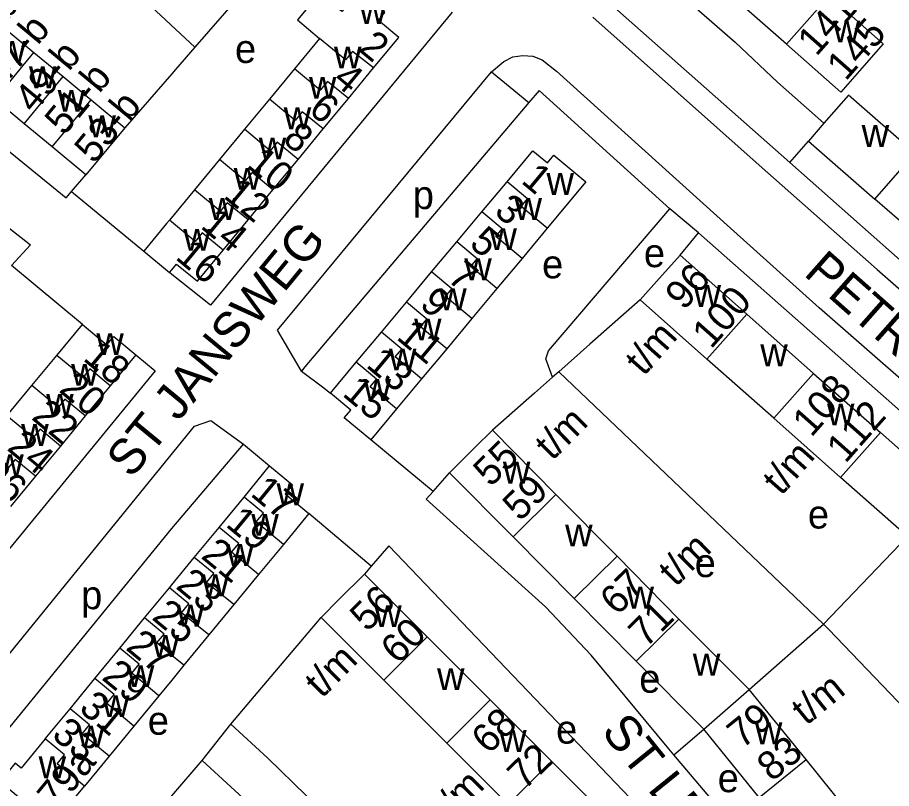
# Model space of a CAD drawing. Extents: x 161141 to 163125, y 381621 to 383200.
# Drawn here: x 162578.3 to 162701.2, y 382067.8 to 382176.1 of the extents above; entities that cross this region are included whole.
import ezdxf

# ---------------------------------------------------------------- set-up
doc = ezdxf.new("R2010")
doc.units = 0
for name, color, linetype in [('BLT_Basislijn', 7, 'Continuous'), ('BLT_Bebouwing', 7, 'Continuous'), ('BLT_Centroide', 7, 'Continuous'), ('BLT_Huisnummer', 7, 'Continuous'), ('BLT_Huisnummer_ tussenligend', 7, 'Continuous'), ('BLT_Huisnummer_reeks', 7, 'Continuous'), ('BLT_Onderverdeling_panden', 7, 'Continuous'), ('BLT_Straatnaam', 7, 'Continuous')]:
    doc.layers.add(name, color=color, linetype=linetype)

msp = doc.modelspace()

# ---------------------------------------------------------------- linework, layer by layer
at = {"layer": 'BLT_Basislijn'}
for p, q in [((162603.24, 382171.92), (162552.11, 382219.68)), ((162627.91, 382207.82), (162686.86, 382155.75)), ((162612.62, 382182.69), (162603.24, 382171.92)), ((162659.18, 382176.13), (162682.55, 382155.38)), ((162603.24, 382171.92), (162600.54, 382168.81)), ((162644.95, 382168.48), (162646.65, 382169.93)), ((162646.65, 382169.93), (162647.92, 382170.57)), ((162647.92, 382170.57), (162649.32, 382170.78)), ((162649.32, 382170.78), (162650.74, 382170.65)), ((162650.74, 382170.65), (162652.07, 382170.16)), ((162652.07, 382170.16), (162654.06, 382168.58)), ((162614.87, 382132.2), (162644.95, 382168.48)), ((162644.95, 382168.48), (162650.18, 382164.18)), ((162678.53, 382146.52), (162654.06, 382168.58)), ((162669.99, 382149.24), (162651.61, 382165.86)), ((162686.86, 382155.75), (162689.47, 382158.75)), ((162682.55, 382155.38), (162699.16, 382140.69)), ((162686.86, 382155.75), (162723.9, 382122.88)), ((162585.92, 382151.66), (162587.92, 382153.99)), ((162585.92, 382151.66), (162596.05, 382143.29)), ((162674.05, 382145.84), (162669.99, 382149.24)), ((162690.97, 382135.31), (162678.53, 382146.52)), ((162671.43, 382142.74), (162674.05, 382145.84)), ((162711.69, 382112.59), (162674.05, 382145.84)), ((162587.43, 382132.98), (162577.47, 382141.26)), ((162699.16, 382140.69), (162721.48, 382120.96)), ((162665.84, 382136.43), (162658.77, 382130.2)), ((162705.55, 382122.59), (162690.97, 382135.31)), ((162618.22, 382126.43), (162614.87, 382132.2)), ((162658.77, 382130.2), (162654.39, 382126.34)), ((162653.5, 382125.56), (162650.99, 382123.34)), ((162654.39, 382126.34), (162653.5, 382125.56)), ((162654.39, 382126.34), (162691.58, 382090.88)), ((162650.99, 382123.34), (162645.07, 382118.13)), ((162603.17, 382118.72), (162605.5, 382119.51)), ((162605.5, 382119.51), (162610.06, 382116.17)), ((162564.06, 382070.63), (162603.17, 382118.72)), ((162636.73, 382109.54), (162627.96, 382116.77)), ((162636.73, 382109.54), (162639.05, 382112.16)), ((162628.03, 382099.03), (162619.27, 382106.45)), ((162691.58, 382090.88), (162703.38, 382103.2)), ((162628.03, 382099.03), (162627.07, 382097.93)), ((162611.6, 382080.77), (162620.99, 382091.84)), ((162681.17, 382081.7), (162691.58, 382090.88)), ((162608.29, 382076.86), (162611.6, 382080.77)), ((162670.57, 382072.53), (162674.76, 382076.14))]:
    msp.add_line(p, q, dxfattribs=at)
for points in [[(162632.9, 382213.4), (162647.43, 382200.65), (162654.07, 382194.55), (162679.17, 382172.65), (162685.13, 382167), (162691.65, 382161.24)], [(162528.71, 382196.77), (162585.17, 382150.79), (162585.92, 382151.66)], [(162523.31, 382189.92), (162527.71, 382186.06), (162546.39, 382170.58), (162580.13, 382144.17), (162577.47, 382141.26)], [(162639.4, 382176.86), (162605.45, 382135.68), (162600, 382140.02), (162599.68, 382140.28)], [(162600.54, 382168.81), (162600, 382168.19), (162593.39, 382160.61)], [(162651.61, 382165.86), (162650.18, 382164.18)], [(162650.18, 382164.18), (162618.7, 382127.04), (162618.22, 382126.43)], [(162653.5, 382125.56), (162652.55, 382128.18), (162652.96, 382129.27), (162669.99, 382149.24)], [(162594.95, 382128.72), (162597.67, 382126.47), (162566.95, 382089.09), (162559.73, 382080.45)], [(162618.22, 382126.43), (162621.18, 382124.21), (162622.29, 382123.35)], [(162569.16, 382066.59), (162600, 382104.33), (162610.06, 382116.17)], [(162610.06, 382116.17), (162613.75, 382113.11)], [(162670.57, 382072.53), (162669.87, 382073.36), (162658.96, 382086.55), (162652.5, 382093.32), (162635.73, 382108.43), (162636.73, 382109.54)], [(162665.45, 382065.37), (162630.49, 382101.88), (162628.03, 382099.03)], [(162691.58, 382090.88), (162692.35, 382090.16), (162725.6, 382055.44)], [(162702.83, 382034.98), (162687.74, 382052.28), (162670.57, 382072.53)], [(162599.62, 382066.34), (162600, 382066.79), (162604.25, 382071.74)]]:
    msp.add_lwpolyline(points, dxfattribs=at)
at = {"layer": 'BLT_Bebouwing'}
for p, q in [((162686.38, 382172.33), (162677.65, 382180.03)), ((162576.15, 382174.87), (162580.61, 382171.18)), ((162620.76, 382173.15), (162617.24, 382168.9)), ((162580.61, 382171.18), (162584.71, 382167.79)), ((162617.24, 382168.9), (162613.73, 382164.65)), ((162624.83, 382164.73), (162628.37, 382169.01)), ((162584.71, 382167.79), (162588.65, 382164.52)), ((162621.29, 382160.45), (162624.83, 382164.73)), ((162579.24, 382161.18), (162575.14, 382164.57)), ((162588.65, 382164.52), (162593.39, 382160.61)), ((162613.73, 382164.65), (162610.21, 382160.4)), ((162583.18, 382157.91), (162579.24, 382161.18)), ((162691.65, 382161.24), (162689.47, 382158.75)), ((162610.21, 382160.4), (162606.69, 382156.15)), ((162617.75, 382156.17), (162621.29, 382160.45)), ((162689.47, 382158.75), (162698.82, 382150.59)), ((162587.92, 382153.99), (162583.18, 382157.91)), ((162606.69, 382156.15), (162603.18, 382151.9)), ((162614.21, 382151.89), (162617.75, 382156.17)), ((162643.59, 382148.81), (162647.13, 382153.03)), ((162603.18, 382151.9), (162599.66, 382147.65)), ((162610.72, 382147.67), (162614.21, 382151.89)), ((162708.16, 382142.43), (162698.82, 382150.59)), ((162640.06, 382144.58), (162643.59, 382148.81)), ((162607.2, 382143.42), (162610.72, 382147.67)), ((162652.75, 382146.5), (162649.22, 382142.27)), ((162636.52, 382140.36), (162640.06, 382144.58)), ((162596.05, 382143.29), (162599.68, 382140.28)), ((162671.43, 382142.74), (162680.81, 382134.43)), ((162649.22, 382142.27), (162645.69, 382138.04)), ((162632.99, 382136.13), (162636.52, 382140.36)), ((162645.69, 382138.04), (162642.17, 382133.81)), ((162675.22, 382128.12), (162665.84, 382136.43)), ((162629.45, 382131.91), (162632.99, 382136.13)), ((162680.81, 382134.43), (162690.2, 382126.12)), ((162583.83, 382128.63), (162587.43, 382132.98)), ((162642.17, 382133.81), (162638.64, 382129.58)), ((162625.92, 382127.68), (162629.45, 382131.91)), ((162638.64, 382129.58), (162635.11, 382125.35)), ((162580.33, 382124.4), (162583.83, 382128.63)), ((162594.95, 382128.72), (162591.35, 382124.37)), ((162684.61, 382119.81), (162675.22, 382128.12)), ((162622.29, 382123.35), (162625.92, 382127.68)), ((162690.2, 382126.12), (162699.59, 382117.82)), ((162576.83, 382120.16), (162580.33, 382124.4)), ((162591.35, 382124.37), (162587.84, 382120.14)), ((162635.11, 382125.35), (162631.58, 382121.12)), ((162631.58, 382121.12), (162627.96, 382116.77)), ((162587.84, 382120.14), (162584.34, 382115.9)), ((162694, 382111.5), (162684.61, 382119.81)), ((162653.99, 382109.12), (162645.07, 382118.13)), ((162699.59, 382117.82), (162708.97, 382109.51)), ((162584.34, 382115.9), (162580.84, 382111.67)), ((162610.15, 382108.74), (162613.75, 382113.11)), ((162647.98, 382103.16), (162639.05, 382112.16)), ((162580.84, 382111.67), (162577.34, 382107.43)), ((162703.38, 382103.2), (162694, 382111.5)), ((162606.66, 382104.49), (162610.15, 382108.74)), ((162662.59, 382100.45), (162653.99, 382109.12)), ((162619.27, 382106.45), (162615.68, 382102.09)), ((162603.16, 382100.25), (162606.66, 382104.49)), ((162615.68, 382102.09), (162612.19, 382097.85)), ((162656.57, 382094.49), (162647.98, 382103.16)), ((162671.24, 382091.6), (162662.59, 382100.45)), ((162612.19, 382097.85), (162608.74, 382093.65)), ((162627.07, 382097.93), (162635.91, 382089.1)), ((162596.17, 382091.76), (162599.67, 382096)), ((162608.74, 382093.65), (162605.22, 382089.38)), ((162665.28, 382085.7), (162656.57, 382094.49)), ((162592.68, 382087.51), (162596.17, 382091.76)), ((162620.99, 382091.84), (162629.82, 382083.01)), ((162681.17, 382081.7), (162671.24, 382091.6)), ((162605.22, 382089.38), (162601.71, 382085.11)), ((162635.91, 382089.1), (162644.74, 382080.27)), ((162589.18, 382083.26), (162592.68, 382087.51)), ((162674.76, 382076.14), (162665.28, 382085.7)), ((162585.69, 382079.02), (162589.18, 382083.26)), ((162629.82, 382083.01), (162638.66, 382074.18)), ((162689.14, 382071.89), (162681.17, 382081.7)), ((162598.19, 382080.84), (162594.68, 382076.57)), ((162644.74, 382080.27), (162653.35, 382071.67)), ((162582.19, 382074.77), (162585.69, 382079.02)), ((162594.68, 382076.57), (162591.21, 382072.37)), ((162604.25, 382071.74), (162608.29, 382076.86)), ((162682.56, 382066.54), (162674.76, 382076.14)), ((162638.66, 382074.18), (162647.26, 382065.58)), ((162591.21, 382072.37), (162587.72, 382068.12)), ((162653.35, 382071.67), (162662.51, 382062.52)), ((162697.12, 382062.07), (162689.14, 382071.89))]:
    msp.add_line(p, q, dxfattribs=at)
for points in [[(162628.37, 382169.01), (162631.91, 382173.29), (162629.03, 382175.67), (162629.96, 382176.8), (162626.28, 382179.84), (162623.89, 382176.94), (162620.77, 382179.52), (162617.66, 382175.76), (162620.76, 382173.15)], [(162692.37, 382179.13), (162700, 382172.4), (162697.32, 382169.35), (162694.01, 382165.6), (162686.38, 382172.33)], [(162704.45, 382157.04), (162695.11, 382165.2), (162691.65, 382161.24)], [(162593.39, 382160.61), (162591.11, 382157.85), (162587.92, 382153.99)], [(162647.13, 382153.03), (162650.76, 382157.38), (162652.8, 382155.67), (162653.7, 382156.75), (162658.18, 382153.01), (162652.75, 382146.5)], [(162599.66, 382147.65), (162599.26, 382147.17), (162596.05, 382143.29)], [(162599.68, 382140.28), (162600, 382140.66), (162600.67, 382141.47), (162603.59, 382139.05), (162607.2, 382143.42)], [(162665.84, 382136.43), (162668.11, 382139), (162671.43, 382142.74)], [(162587.43, 382132.98), (162590.87, 382130.14), (162591.83, 382131.3), (162594.95, 382128.72)], [(162627.96, 382116.77), (162624.24, 382119.87), (162625.15, 382120.96), (162622.29, 382123.35)], [(162639.05, 382112.16), (162642.61, 382115.68), (162645.07, 382118.13)], [(162613.75, 382113.11), (162616.96, 382110.46), (162615.93, 382109.21), (162619.27, 382106.45)], [(162599.67, 382096), (162600, 382096.41), (162603.16, 382100.25)], [(162627.07, 382097.93), (162623.54, 382094.39), (162620.99, 382091.84)], [(162601.71, 382085.11), (162600, 382083.04), (162598.19, 382080.84)], [(162608.29, 382076.86), (162613.5, 382072.07), (162618.87, 382066.82), (162630.37, 382054.47), (162639.89, 382042.84)], [(162582.19, 382074.77), (162578.82, 382070.68), (162577.97, 382071.38), (162575.85, 382068.81), (162579.88, 382065.49), (162580.74, 382066.55), (162584.13, 382063.76), (162587.72, 382068.12)], [(162662.04, 382005.64), (162630.19, 382044.68), (162619.23, 382057.23), (162612.32, 382064.36), (162604.25, 382071.74)]]:
    msp.add_lwpolyline(points, dxfattribs=at)
at = {"layer": 'BLT_Onderverdeling_panden'}
for p, q in [((162686.38, 382172.33), (162692.37, 382179.13)), ((162575.14, 382164.57), (162580.61, 382171.18)), ((162579.24, 382161.18), (162584.71, 382167.79)), ((162583.18, 382157.91), (162588.65, 382164.52)), ((162698.82, 382150.59), (162704.45, 382157.04)), ((162675.22, 382128.12), (162680.81, 382134.43)), ((162684.61, 382119.81), (162690.2, 382126.12)), ((162694, 382111.5), (162699.59, 382117.82)), ((162647.98, 382103.16), (162653.99, 382109.12)), ((162656.57, 382094.49), (162662.59, 382100.45)), ((162665.28, 382085.7), (162671.24, 382091.6)), ((162629.82, 382083.01), (162635.91, 382089.1)), ((162674.76, 382076.14), (162681.17, 382081.7)), ((162638.66, 382074.18), (162644.74, 382080.27)), ((162647.26, 382065.58), (162653.35, 382071.67)), ((162682.56, 382066.54), (162689.14, 382071.89))]:
    msp.add_line(p, q, dxfattribs=at)
for points in [[(162628.37, 382169.01), (162625.38, 382171.34), (162624.39, 382170.14), (162620.76, 382173.15)], [(162624.83, 382164.73), (162621.86, 382167.09), (162620.87, 382165.89), (162617.24, 382168.9)], [(162621.29, 382160.45), (162618.34, 382162.84), (162617.36, 382161.64), (162613.73, 382164.65)], [(162617.75, 382156.17), (162614.83, 382158.59), (162613.84, 382157.39), (162610.21, 382160.4)], [(162614.21, 382151.89), (162611.31, 382154.34), (162610.33, 382153.14), (162606.69, 382156.15)], [(162652.75, 382146.5), (162649.08, 382149.56), (162649.99, 382150.64), (162647.13, 382153.03)], [(162610.72, 382147.67), (162607.8, 382150.09), (162606.81, 382148.89), (162603.18, 382151.9)], [(162649.22, 382142.27), (162645.55, 382145.34), (162646.45, 382146.42), (162643.59, 382148.81)], [(162607.2, 382143.42), (162604.28, 382145.84), (162603.3, 382144.64), (162599.66, 382147.65)], [(162645.69, 382138.04), (162642.01, 382141.11), (162642.92, 382142.19), (162640.06, 382144.58)], [(162642.17, 382133.81), (162638.48, 382136.89), (162639.38, 382137.97), (162636.52, 382140.36)], [(162638.64, 382129.58), (162634.94, 382132.66), (162635.85, 382133.74), (162632.99, 382136.13)], [(162635.11, 382125.35), (162631.41, 382128.44), (162632.31, 382129.52), (162629.45, 382131.91)], [(162591.35, 382124.37), (162588.48, 382126.74), (162587.52, 382125.58), (162583.83, 382128.63)], [(162631.58, 382121.12), (162627.87, 382124.21), (162628.77, 382125.29), (162625.92, 382127.68)], [(162587.84, 382120.14), (162584.98, 382122.51), (162584.02, 382121.34), (162580.33, 382124.4)], [(162584.34, 382115.9), (162581.48, 382118.27), (162580.52, 382117.11), (162576.83, 382120.16)], [(162580.84, 382111.67), (162577.97, 382114.04), (162577.01, 382112.87), (162573.32, 382115.92)], [(162615.68, 382102.09), (162611.86, 382105.24), (162612.89, 382106.49), (162610.15, 382108.74)], [(162612.19, 382097.85), (162608.37, 382100.99), (162609.4, 382102.24), (162606.66, 382104.49)], [(162608.74, 382093.65), (162604.87, 382096.74), (162605.9, 382098), (162603.16, 382100.25)], [(162605.22, 382089.38), (162601.38, 382092.5), (162602.4, 382093.75), (162600.52, 382095.3), (162599.67, 382096)], [(162601.71, 382085.11), (162600, 382086.51), (162597.88, 382088.25), (162598.91, 382089.5), (162596.17, 382091.76)], [(162598.19, 382080.84), (162594.39, 382084.01), (162595.41, 382085.26), (162592.68, 382087.51)], [(162594.68, 382076.57), (162590.89, 382079.76), (162591.92, 382081.01), (162589.18, 382083.26)], [(162591.21, 382072.37), (162587.4, 382075.51), (162588.42, 382076.76), (162585.69, 382079.02)], [(162587.72, 382068.12), (162583.9, 382071.27), (162584.93, 382072.52), (162582.19, 382074.77)]]:
    msp.add_lwpolyline(points, dxfattribs=at)

# ---------------------------------------------------------------- texts
at = {"layer": 'BLT_Centroide'}
for s, p in [('w', (162626.33, 382175.19)), ('w', (162692.91, 382172.59)), ('w', (162575.64, 382169.72)), ('e', (162608.88, 382169.71)), ('w', (162622.8, 382168.94)), ('w', (162579.92, 382166.17)), ('w', (162619.27, 382164.69)), ('w', (162583.95, 382162.86)), ('w', (162615.73, 382160.41)), ('w', (162588.28, 382159.27)), ('w', (162696.96, 382157.91)), ('w', (162612.22, 382156.16)), ('w', (162608.69, 382151.91)), ('w', (162652.66, 382151.19)), ('p', (162633.86, 382149.19)), ('w', (162605.19, 382147.66)), ('w', (162648.17, 382147.66)), ('w', (162601.62, 382143.34)), ('w', (162644.64, 382143.42)), ('e', (162666.35, 382141.03)), ('e', (162652.04, 382139.46)), ('w', (162641.11, 382139.2)), ('w', (162637.58, 382134.97)), ('w', (162673.33, 382135.44)), ('w', (162634.05, 382130.75)), ('w', (162589.39, 382128.69)), ('w', (162630.52, 382126.52)), ('w', (162682.71, 382127.12)), ('w', (162585.84, 382124.38)), ('w', (162626.94, 382122.23)), ('w', (162582.34, 382120.16)), ('w', (162692.09, 382118.81)), ('w', (162578.83, 382115.91)), ('w', (162575.33, 382111.69)), ('w', (162646.53, 382110.64)), ('w', (162614.72, 382107.59)), ('e', (162689.4, 382104.32)), ('w', (162611.17, 382103.3)), ('w', (162655.28, 382101.8)), ('w', (162607.67, 382099.08)), ('e', (162673.49, 382097.5)), ('w', (162604.2, 382094.81)), ('p', (162587.25, 382092.99)), ('w', (162663.91, 382093.09)), ('w', (162600.7, 382090.55)), ('w', (162628.45, 382090.47)), ('w', (162597.19, 382086.28)), ('w', (162673.23, 382083.66)), ('w', (162593.69, 382082.05)), ('w', (162637.28, 382081.62)), ('e', (162665.7, 382081.26)), ('w', (162590.19, 382077.83)), ('e', (162596.62, 382075.36)), ('w', (162586.7, 382073.58)), ('e', (162654.01, 382074.11)), ('w', (162681.95, 382074.02)), ('w', (162646, 382072.94)), ('w', (162581.28, 382069.25)), ('e', (162676.73, 382067.29))]:
    msp.add_text(s, height=4, dxfattribs=at).set_placement(p)
at = {"layer": 'BLT_Huisnummer'}
for s, rotation, p in [('2', 320.4049, (162626.08, 382171.53)), ('6', 320.4049, (162619.05, 382162.86)), ('10', 320.404, (162610.38, 382155.21)), ('1', 320.178, (162648.95, 382152.97)), ('5', 320.1746, (162641.66, 382144.06)), ('16', 320.4054, (162600.35, 382142.26)), ('9', 320.1764, (162634.67, 382135.55)), ('18', 320.2064, (162587.37, 382128.05)), ('15', 320.1763, (162623.83, 382123.07)), ('22', 320.2056, (162580.13, 382119.78)), ('26', 320.2048, (162572.89, 382111.41)), ('17', 320.5398, (162610.9, 382109.03)), ('21', 320.5398, (162603.96, 382100.27)), ('25', 320.5383, (162597.04, 382091.67)), ('29', 320.5398, (162590, 382083.22)), ('33', 320.5398, (162582.96, 382075.06)), ('79a', 50.5399, (162583.85, 382064.59))]:
    msp.add_text(s, height=4, rotation=rotation, dxfattribs=at).set_placement(p)
at = {"layer": 'BLT_Huisnummer_ tussenligend'}
for s, rotation, p in [('4', 320.4049, (162622.45, 382167.05)), ('8', 320.4049, (162615.43, 382158.71)), ('12', 320.404, (162607.11, 382150.88)), ('3', 320.178, (162645.15, 382148.59)), ('14', 320.404, (162603.89, 382146.63)), ('7', 320.1746, (162638.55, 382139.24)), ('11', 320.1764, (162631.42, 382131.02)), ('13', 320.1782, (162627.15, 382127.11)), ('20', 320.2064, (162584, 382123.63)), ('24', 320.2056, (162576.68, 382115.45)), ('19', 320.5398, (162607.42, 382104.72)), ('23', 320.5398, (162600.41, 382096.03)), ('27', 320.5383, (162593.37, 382087.42)), ('31', 320.5398, (162586.79, 382078.79))]:
    msp.add_text(s, height=4, rotation=rotation, dxfattribs=at).set_placement(p)
at = {"layer": 'BLT_Huisnummer_reeks'}
for s, rotation, p in [('45-b', 50.3836, (162571.9, 382169.58)), ('141', 48.6023, (162690.59, 382170.52)), ('47-b', 50.387, (162576.24, 382166.15)), ('145', 48.5996, (162694.71, 382167.06)), ('49-b', 50.387, (162580.62, 382162.48)), ('51-b', 50.381, (162584.88, 382159.38)), ('53-b', 50.4033, (162589.06, 382155.41)), ('96', 48.49, (162671.99, 382134.84)), ('100', 48.4906, (162675.79, 382129.43)), ('t/m', 48.4912, (162666.34, 382125.62)), ('108', 48.4906, (162689.88, 382117.02)), ('112', 48.4912, (162694.68, 382113.36)), ('t/m', 44.7465, (162653.45, 382113.74)), ('55', 44.7465, (162644.8, 382110.03)), ('t/m', 48.4912, (162685.66, 382108.82)), ('59', 44.7465, (162648.93, 382105.21)), ('t/m', 44.7465, (162670.82, 382096.02)), ('67', 44.7465, (162662.61, 382091.97)), ('56', 45.0235, (162627.47, 382089.68)), ('71', 44.7465, (162666.62, 382087.46)), ('60', 45.0188, (162631.81, 382085.11)), ('t/m', 45.0188, (162621.1, 382080.37)), ('t/m', 39.0965, (162689.16, 382076.56)), ('68', 45.0235, (162644.56, 382072.48)), ('79', 39.0922, (162680.15, 382073.29)), ('72', 44.125, (162649.56, 382067.48)), ('83', 39.0965, (162684.32, 382068.66)), ('t/m', 45.0188, (162638.93, 382062.76))]:
    msp.add_text(s, height=4, rotation=rotation, dxfattribs=at).set_placement(p)
at = {"layer": 'BLT_Straatnaam'}
for s, rotation, p in [('ST JANSWEG', 50.6102, (162594.3, 382111.21)), ('PETRUS DONDERSSTRAAT', 318.5406, (162688.67, 382139.98)), ('ST LEONARDUSSTRAAT', 308.946, (162660.23, 382075.76))]:
    msp.add_text(s, height=5, rotation=rotation, dxfattribs=at).set_placement(p)

doc.saveas('drawing.dxf')
